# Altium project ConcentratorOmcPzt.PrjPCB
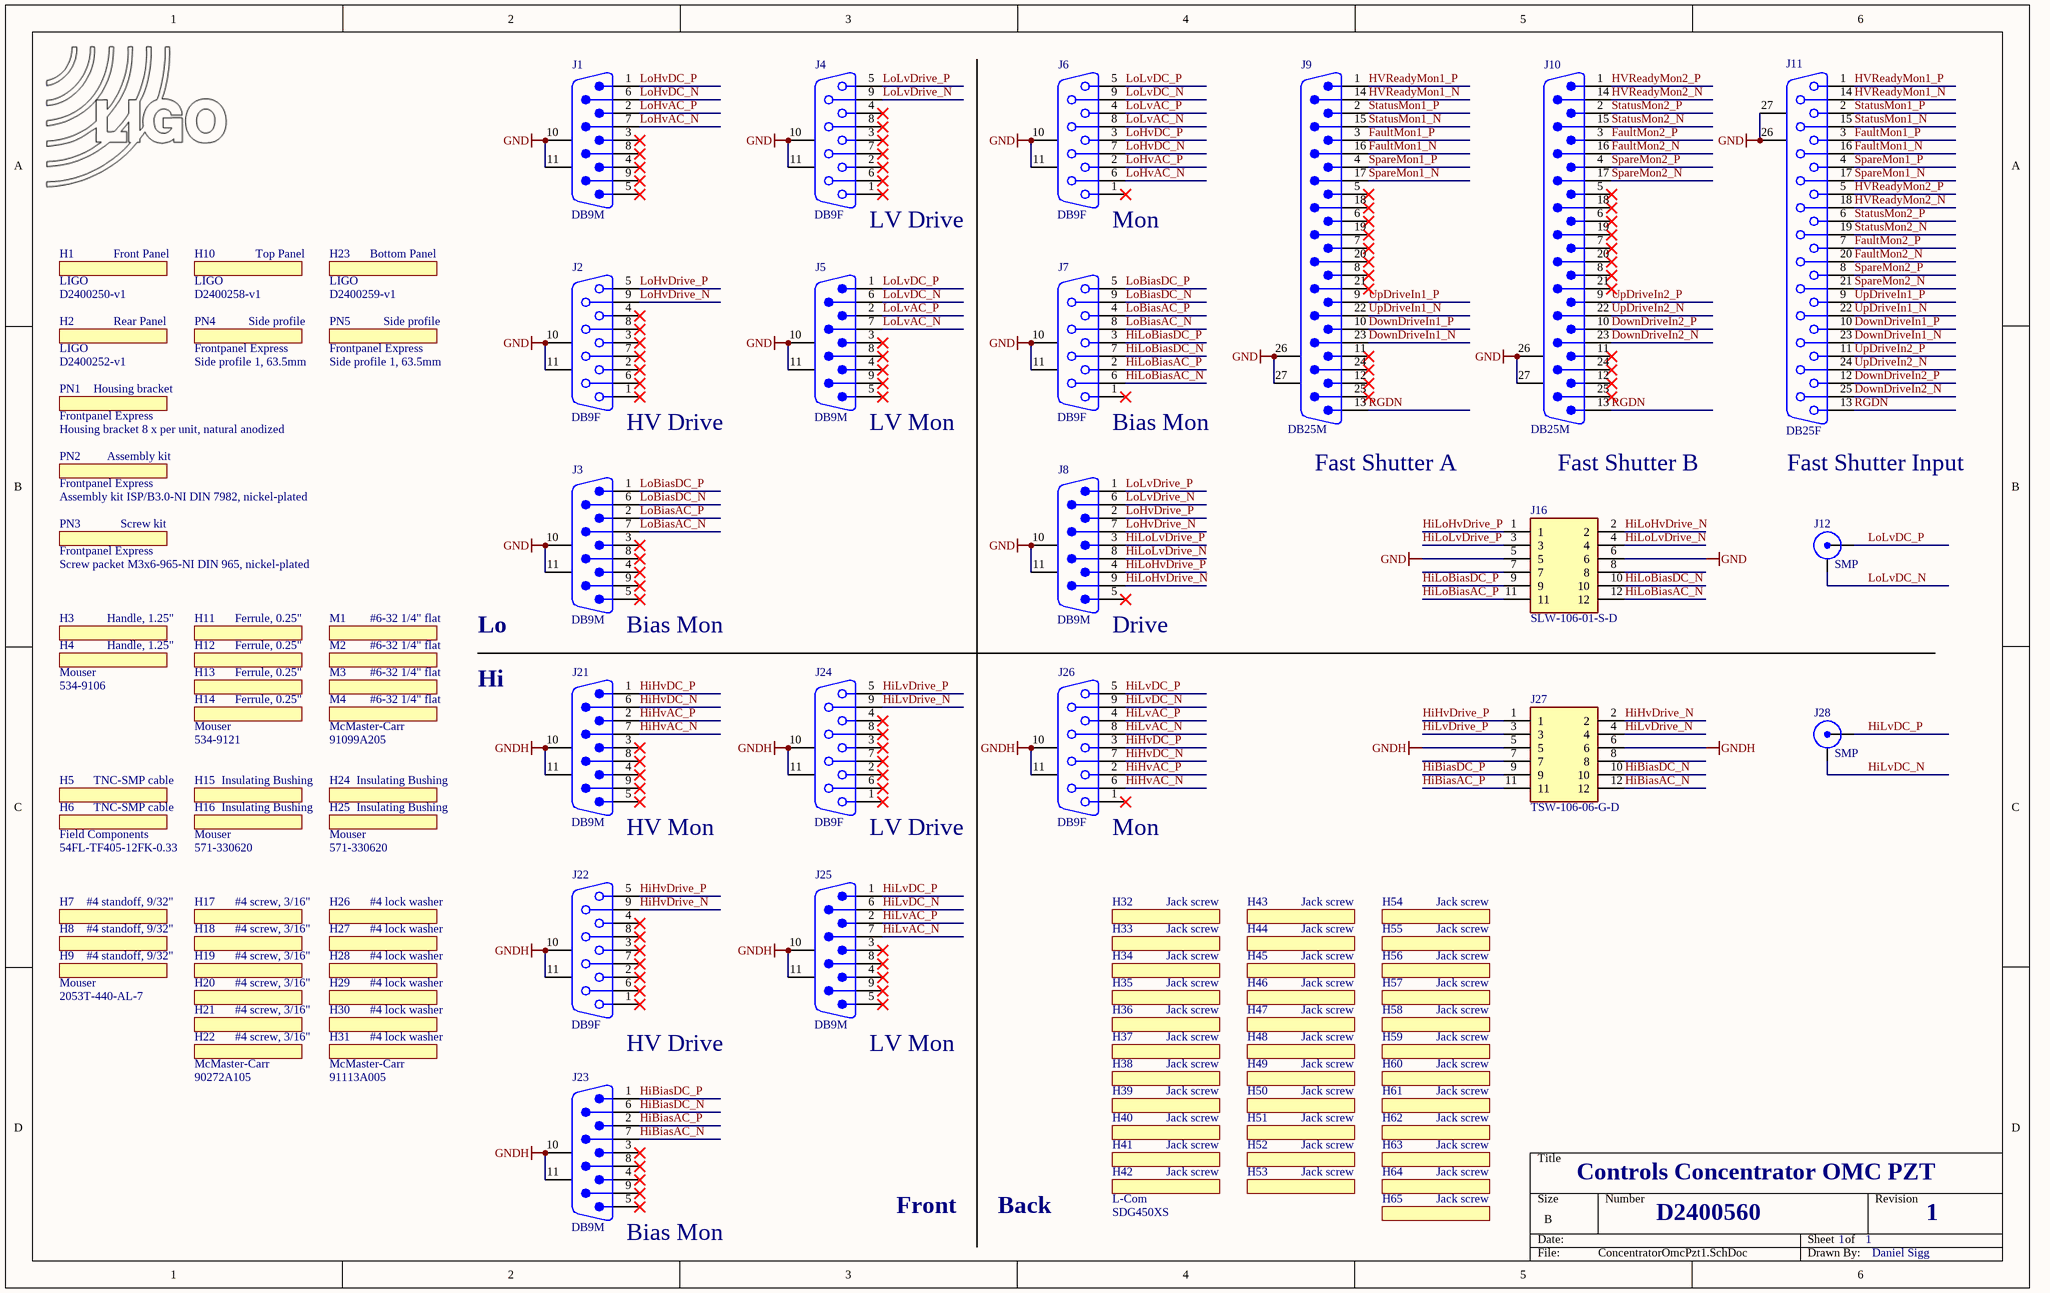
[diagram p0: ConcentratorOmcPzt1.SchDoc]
DCC: D2400560
1 sheet, 96 parts. Net scope: global (net labels, ports and power ports of the same name join across sheets).
Board file: ConcentratorOmcPzt.PcbDoc

## Sheet ConcentratorOmcPzt1.SchDoc: D1100982
size B; Engineer: Daniel Sigg; DocumentNumber: D2400560; Revision: 1; SheetNumber: 1; SheetTotal: 1; PageSetup: Record=PageOptions¦CenterHorizontal=True¦CenterVertical=True¦PrintScale=1.12¦XCorrection=1.00¦YCorrection=1.00¦PrintKind=0¦BorderSize=5000000¦LeftOffset=0¦BottomOffset=0¦Orientation=2¦PaperLength=1000¦PaperWidth=1000¦Scale=100¦PaperSource=7¦PrintQuality=-4¦MediaType=1¦DitherType=10¦PaperKind=Letter¦PrintScaleMode=1

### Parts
H1  Front Panel  Part Number: D2400250-v1  Distributor: LIGO  (mechanical)
H2  Rear Panel  Part Number: D2400252-v1  Distributor: LIGO  (mechanical)
H3  Handle, 1.25"  (mechanical)
H4  Handle, 1.25"  Part Number: 534-9106  Distributor: Mouser  (mechanical)
H5  TNC-SMP cable  (mechanical)
H6  TNC-SMP cable  Part Number: 54FL-TF405-12FK-0.33  Distributor: Field Components  (mechanical)
H7  #4 standoff, 9/32"  (mechanical)
H8  #4 standoff, 9/32"  (mechanical)
H9  #4 standoff, 9/32"  Part Number: 2053T-440-AL-7  Distributor: Mouser  (mechanical)
H10  Top Panel  Part Number: D2400258-v1  Distributor: LIGO  (mechanical)
H11  Ferrule, 0.25"  (mechanical)
H12  Ferrule, 0.25"  (mechanical)
H13  Ferrule, 0.25"  (mechanical)
H14  Ferrule, 0.25"  Part Number: 534-9121  Distributor: Mouser  (mechanical)
H15  Insulating Bushing  (mechanical)
H16  Insulating Bushing  Part Number: 571-330620  Distributor: Mouser  (mechanical)
H17  #4 screw, 3/16"  (mechanical)
H18  #4 screw, 3/16"  (mechanical)
H19  #4 screw, 3/16"  (mechanical)
H20  #4 screw, 3/16"  (mechanical)
H21  #4 screw, 3/16"  (mechanical)
H22  #4 screw, 3/16"  Part Number: 90272A105  Distributor: McMaster-Carr  (mechanical)
H23  Bottom Panel  Part Number: D2400259-v1  Distributor: LIGO  (mechanical)
H24  Insulating Bushing  (mechanical)
H25  Insulating Bushing  Part Number: 571-330620  Distributor: Mouser  (mechanical)
H26  #4 lock washer  (mechanical)
H27  #4 lock washer  (mechanical)
H28  #4 lock washer  (mechanical)
H29  #4 lock washer  (mechanical)
H30  #4 lock washer  (mechanical)
H31  #4 lock washer  Part Number: 91113A005  Distributor: McMaster-Carr  (mechanical)
H32  Jack screw  (mechanical)
H33  Jack screw  (mechanical)
H34  Jack screw  (mechanical)
H35  Jack screw  (mechanical)
H36  Jack screw  (mechanical)
H37  Jack screw  (mechanical)
H38  Jack screw  (mechanical)
H39  Jack screw  (mechanical)
H40  Jack screw  (mechanical)
H41  Jack screw  (mechanical)
H42  Jack screw  Part Number: SDG450XS  Distributor: L-Com  (mechanical)
H43  Jack screw  (mechanical)
H44  Jack screw  (mechanical)
H45  Jack screw  (mechanical)
H46  Jack screw  (mechanical)
H47  Jack screw  (mechanical)
H48  Jack screw  (mechanical)
H49  Jack screw  (mechanical)
H50  Jack screw  (mechanical)
H51  Jack screw  (mechanical)
H52  Jack screw  (mechanical)
H53  Jack screw  (mechanical)
H54  Jack screw  (mechanical)
H55  Jack screw  (mechanical)
H56  Jack screw  (mechanical)
H57  Jack screw  (mechanical)
H58  Jack screw  (mechanical)
H59  Jack screw  (mechanical)
H60  Jack screw  (mechanical)
H61  Jack screw  (mechanical)
H62  Jack screw  (mechanical)
H63  Jack screw  (mechanical)
H64  Jack screw  (mechanical)
H65  Jack screw  (mechanical)
J1  DB9M  [DB9M-RA]
J2  DB9F  [DB9F-RA]
J3  DB9M  [DB9M-RA]
J4  DB9F  [DB9F-RA]
J5  DB9M  [DB9M-RA]
J6  DB9F  [DB9F-RA]
J7  DB9F  [DB9F-RA]
J8  DB9M  [DB9M-RA]
J9  DB25M  [DB25M-RA]
J10  DB25M  [DB25M-RA]
J11  DB25F  [DB25F-RA]
J12  SMP  [SMP]
J16  SLW-106-01-S-D  [SLW-106-01-X-D]
J21  DB9M  [DB9M-RA]
J22  DB9F  [DB9F-RA]
J23  DB9M  [DB9M-RA]
J24  DB9F  [DB9F-RA]
J25  DB9M  [DB9M-RA]
J26  DB9F  [DB9F-RA]
J27  TSW-106-06-G-D  [HDRV12W64P254_2X6_1524X495X521P]
J28  SMP  [SMP]
LOGO1  LIGO logo  [LIGO_LOGO]  (value not drawn)  (no BOM)
M1  #6-32 1/4" flat  (mechanical)
M2  #6-32 1/4" flat  (mechanical)
M3  #6-32 1/4" flat  (mechanical)
M4  #6-32 1/4" flat  Part Number: 91099A205  Distributor: McMaster-Carr  (mechanical)
PN1  Housing bracket  Part Number: Housing bracket 8 x per unit, natural anodized  Distributor: Frontpanel Express  (mechanical)
PN2  Assembly kit  Distributor: Frontpanel Express  (mechanical)
PN3  Screw kit  Distributor: Frontpanel Express  (mechanical)
PN4  Side profile  Part Number: Side profile 1, 63.5mm  Distributor: Frontpanel Express  (mechanical)
PN5  Side profile  Part Number: Side profile 1, 63.5mm  Distributor: Frontpanel Express  (mechanical)

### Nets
GND: J1.10(MH1) J1.11(MH2) J2.10(MH1) J2.11(MH2) J3.10(MH1) J3.11(MH2) J4.10(MH1) J4.11(MH2) J5.10(MH1) J5.11(MH2) J6.10(MH1) J6.11(MH2) J7.10(MH1) J7.11(MH2) J8.10(MH1) J8.11(MH2) J9.26(MH1) J9.27(MH2) J10.26(MH1) J10.27(MH2) J11.26(MH1) J11.27(MH2) J16.5 J16.6
GNDH: J21.10(MH1) J21.11(MH2) J22.10(MH1) J22.11(MH2) J23.10(MH1) J23.11(MH2) J24.10(MH1) J24.11(MH2) J25.10(MH1) J25.11(MH2) J26.10(MH1) J26.11(MH2) J27.5 J27.6
DownDriveIn1_N: J9.23 J11.23
DownDriveIn1_P: J9.10 J11.10
DownDriveIn2_N: J10.23 J11.25
DownDriveIn2_P: J10.10 J11.12
FaultMon1_N: J9.16 J11.16
FaultMon1_P: J9.3 J11.3
FaultMon2_N: J10.16 J11.20
FaultMon2_P: J10.3 J11.7
HiBiasAC_N: J23.7 J27.12
HiBiasAC_P: J23.2 J27.11
HiBiasDC_N: J23.6 J27.10
HiBiasDC_P: J23.1 J27.9
HiHvAC_N: J21.7 J26.6
HiHvAC_P: J21.2 J26.2
HiHvDC_N: J21.6 J26.7
HiHvDC_P: J21.1 J26.3
HiHvDrive_N: J22.9 J27.2
HiHvDrive_P: J22.5 J27.1
HiLoBiasAC_N: J7.6 J16.12
HiLoBiasAC_P: J7.2 J16.11
HiLoBiasDC_N: J7.7 J16.10
HiLoBiasDC_P: J7.3 J16.9
HiLoHvDrive_N: J8.9 J16.2
HiLoHvDrive_P: J8.4 J16.1
HiLoLvDrive_N: J8.8 J16.4
HiLoLvDrive_P: J8.3 J16.3
HiLvAC_N: J25.7 J26.8
HiLvAC_P: J25.2 J26.4
HiLvDC_N: J25.6 J26.9 J28.2(Y)
HiLvDC_P: J25.1 J26.5 J28.1(X)
HiLvDrive_N: J24.9 J27.4
HiLvDrive_P: J24.5 J27.3
HVReadyMon1_N: J9.14 J11.14
HVReadyMon1_P: J9.1 J11.1
HVReadyMon2_N: J10.14 J11.18
HVReadyMon2_P: J10.1 J11.5
LoBiasAC_N: J3.7 J7.8
LoBiasAC_P: J3.2 J7.4
LoBiasDC_N: J3.6 J7.9
LoBiasDC_P: J3.1 J7.5
LoHvAC_N: J1.7 J6.6
LoHvAC_P: J1.2 J6.2
LoHvDC_N: J1.6 J6.7
LoHvDC_P: J1.1 J6.3
LoHvDrive_N: J2.9 J8.7
LoHvDrive_P: J2.5 J8.2
LoLvAC_N: J5.7 J6.8
LoLvAC_P: J5.2 J6.4
LoLvDC_N: J5.6 J6.9 J12.2(Y)
LoLvDC_P: J5.1 J6.5 J12.1(X)
LoLvDrive_N: J4.9 J8.6
LoLvDrive_P: J4.5 J8.1
RGDN: J9.13 J10.13 J11.13
SpareMon1_N: J9.17 J11.17
SpareMon1_P: J9.4 J11.4
SpareMon2_N: J10.17 J11.21
SpareMon2_P: J10.4 J11.8
StatusMon1_N: J9.15 J11.15
StatusMon1_P: J9.2 J11.2
StatusMon2_N: J10.15 J11.19
StatusMon2_P: J10.2 J11.6
UpDriveIn1_N: J9.22 J11.22
UpDriveIn1_P: J9.9 J11.9
UpDriveIn2_N: J10.22 J11.24
UpDriveIn2_P: J10.9 J11.11

Not connected (* = marked no-connect by the designer): J1 3* 4* 5* 8* 9*; J2 1* 2* 3* 4* 6* 7* 8*; J3 3* 4* 5* 8* 9*; J4 1* 2* 3* 4* 6* 7* 8*; J5 3* 4* 5* 8* 9*; J6 1*; J7 1*; J8 5*; J9 5* 6* 7* 8* 11* 12* 18* 19* 20* 21* 24* 25*; J10 5* 6* 7* 8* 11* 12* 18* 19* 20* 21* 24* 25*; J16 7 8; J21 3* 4* 5* 8* 9*; J22 1* 2* 3* 4* 6* 7* 8*; J23 3* 4* 5* 8* 9*; J24 1* 2* 3* 4* 6* 7* 8*; J25 3* 4* 5* 8* 9*; J26 1*; J27 7 8

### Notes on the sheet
- (near J4) LV Drive
- (near J6) Mon
- (near J2) HV Drive
- (near J5) LV Mon
- (near J7) Bias Mon
- (near J9) Fast Shutter A
- Fast Shutter B
- (near J11) Fast Shutter Input
- Lo
- (near J3) Bias Mon
- (near J8) Drive
- Hi
- (near J21) HV Mon
- (near J24) LV Drive
- (near J26) Mon
- HV Drive
- (near J25) LV Mon
- Controls Concentrator OMC PZT
- (near J23) Bias Mon
- Front
- Back
- D2400560
- 1
- Daniel Sigg

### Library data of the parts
H1 H2 H9 H10 H22 H23 H31 H42 = Partlist: Mounting hardware
H3 = Partlist: Rack handle 1.5U; Part Number: 534-9106
H4 = Partlist: Rack handle 1.5U
H5 = Partlist: SMP Right Angle Female Plug To TNC Female Bulkhead Jack TFLEX-405 Coaxial Cable Assembly; Part Number: 54FL-TF405-12FK-0.33
H6 = Partlist: SMP Right Angle Female Plug To TNC Female Bulkhead Jack TFLEX-405 Coaxial Cable Assembly
H7 H8 = Partlist: Mounting hardware; Part Number: 2053T-440-AL-7
H11-H13 = Partlist: Ferrule; Part Number: 534-9121
H14 = Partlist: Ferrule
H15 H24 = Partlist: RF Connector Accessories Insulating Bushing TE 330620; Part Number: 571-330620
H16 H25 = Partlist: RF Connector Accessories Insulating Bushing TE 330620
H17-H21 = Partlist: Mounting hardware; Part Number: 90272A105
H26-H30 = Partlist: Mounting hardware; Part Number: 91113A005
H32-H41 H43-H65 = Partlist: Mounting hardware; Part Number: SDG450XS
J1 J3 J5 J8 J21 J23 J25 = DB9M: Plug Assembly, 9 Position, Right Angle, .318 Series; Part Number: 571-5747840-4
J2 J4 J6 J7 J22 J24 J26 = DB9F: Receptacle Assembly, 9 Position, Right Angle, .318 Series; Part Number: 571-5747844-4
J9 J10 = DB25M: Plug Assembly, 25 Position, Right Angle, .318 Series; Part Number: 571-5747842-4
J11 = DB25F: Receptacle Assembly, 25 Position, Right Angle, .318 Series; Part Number: 571-5747846-4
J12 J28 = SMP: SMP, PCB Mount; Part Number: 538-73415-3310
J16 = SLW-106-01-S-D: Connector; Manufacturer_Name: SAMTEC; Part Number: 200-SLW10601SD
J27 = TSW-106-06-G-D: Connector; Manufacturer_Name: SAMTEC; Part Number: 200-TSW10606GD
LOGO1 = LIGO_logo
M1-M3 = Partlist: #6-32 1/4" flat head screw; Part Number: 91099A205
M4 = Partlist: #6-32 1/4" flat head screw
PN1 = Partlist: Housing bracket, 8 pieces
PN2 = Partlist: Assembly kit ISP/B3.0-NI DIN 7982, nickel-plated
PN3 = Partlist: Screw packet M3x6-965-NI DIN 965, nickel-plated
PN4 PN5 = Partlist: Side profile 1, anodized, 150mm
